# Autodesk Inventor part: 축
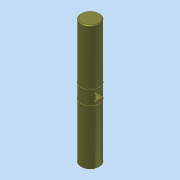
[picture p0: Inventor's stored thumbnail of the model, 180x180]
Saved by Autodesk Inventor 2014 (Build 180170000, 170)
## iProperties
Company: 한국ATC센터
Created: 2015-04
Part Number: 축
Document SubType Name: Modeling
Designer: KYOUNG IL JANG
Density: 7.85 g/cm^3
Material: 강
Appearance: 티타늄
Author: KYOUNG IL JANG
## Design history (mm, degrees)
sketch "스케치1"
  geometry: C1 r 11 at (0, 0); 1 further point
  constraints: 1 centre point, 1 coincident
  dimensions: "d0" = 22 diameter of C1
extrude "돌출1" new body sketch "스케치1" stored distance "d1" = 150; taper "d2" = 0 deg
sketch "스케치2"
  geometry: L1 (-10.247, -4)-(10.247, -4); L2 (-10.247, 4)-(10.247, 4); A1 r 11 centre (0, 0) between (-10.247, -4) and (10.247, -4) reference; 1 further point
  constraints: 4 end point, 4 point on circle, 2 parallel, 1 horizontal
  dimensions: "d3" = 8 distance between parallel lines of L2 L1
extrude "돌출2" cut sketch "스케치2" stored distance "d4" = 8; taper "d5" = 0 deg
sketch "스케치3"
  geometry: 5 further points
hole "구멍1" sketch "스케치3" at (-4, 4), (4, 4), (4, -4), (-4, -4) diameter "d6" = 2; stored, may be unused: countersink angle "d10" = 90 deg, drill point angle "d12" = 118 deg; dims "d7" = 6, "d8" = 4, "d9" = 2, "d11" = 8
chamfer "모따기1" distance "d13" = 1; stored, may be unused: second distance "d14" = 2, angle "d15" = 45 deg
sketch "스케치4"
  geometry: L1 (-10, 9)-(-11, 9); L2 (-11, 9)-(-11, 7.8); L3 (-11, 7.8)-(-10, 7.8); L4 (-10, 7.8)-(-10, 9); L5 (-10, 75)-(10, 75) reference; L6 (0, -10)-(0, 60) reference; 1 further point
  constraints: 8 end point, 2 parallel, 1 horizontal, 1 perpendicular
  dimensions: "d16" = 7.8 distance from line of L3 point (0, 0); "d17" = 67.2 distance between parallel lines of L3 L5 (derived); "d18" = 11 distance from line of point (0, 0) L2; "d19" = 1 distance of L2.end L3.end; "d20" = 1.2 distance of L1.end L2.end
revolve "회전1" sketch "스케치4" stored, may be unused: angle "d21" = 90 deg
node "솔리드1"
mirror "대칭1"
mirror "대칭2"
